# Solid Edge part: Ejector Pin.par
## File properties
Title: Ejector Pin
Author: Dan
Template: FH Insert .par
Last saved by: Dan
Revision: 29
Application: Solid Edge
Density: 7833.000 kg/m^3
Accuracy: 0.990
Material: Steel
Face Style: Steel
Fill Style: ANSI32(Steel)
Virtual Style: Machined steel
Coef. of Thermal Exp: 1.3e-05
Thermal Conductivity: 32.0
Specific Heat: 481.0
Modulus of Elasticity: 199947953000.0
Poisson's Ratio: 0.29
Yield Stress: 262000766.0
Ultimate Stress: 358527364.0
Elongation: 0.0
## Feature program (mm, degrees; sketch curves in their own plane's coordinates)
sketch for "unnamed Protrusion 1" plane through (0, 0, 0) normal (1, 0, 0) x-axis (0, 1, 0)
extrude "unnamed Protrusion 1" add finite 136.2 along -normal
sketch for "ExtrudedProtrusion_4" plane through (-136.2, 0, 0) normal (-1, 0, 0) x-axis (0, -1, 0)
extrude "ExtrudedProtrusion_4" add finite 5 along -normal
sketch for "ExtrudedProtrusion_5" plane through (-136.2, 0, 0) normal (-1, 0, 0) x-axis (0, -1, 0)
extrude "ExtrudedProtrusion_5" add finite 50 along -normal
chamfer "Chamfer_1" setback 5
sketch for "Hole_2" plane through (-136.2, 0, 0) normal (-1, 0, 0) x-axis (0, 0, -1)
  circle centre (0, 0) radius 12.5
hole "Hole_2" finite
sketch for "ExtrudedCutout_3" plane through (-136.2, 0, 0) normal (-1, 0, 0) x-axis (0, 0, -1)
  circle centre (0, 0) radius 12.5
extrude "ExtrudedCutout_3" cut finite 2.2 along -normal
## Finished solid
Body 1: solid body, 12 faces, 11 edges, 1 vertex.
  Faces by surface: cylinder 5, plane 5, cone 2
  Edges by curve: circle 11
Bounding box of the edges (mm): 136.200 x 45.000 x 45.000, from (-136.2, -22.5, -22.5) to (0, 22.5, 22.5).
Cylindrical faces by radius (mm): R9 x1, R12.5 x2, R19.5 x1, R22.5 x1
Conical faces (half-angle, radius in mm at the cone's reference point): 45 deg R14.5 x1, 59 deg R9 x1
Planar faces by outward normal: +x 3, -x 2
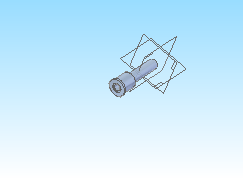
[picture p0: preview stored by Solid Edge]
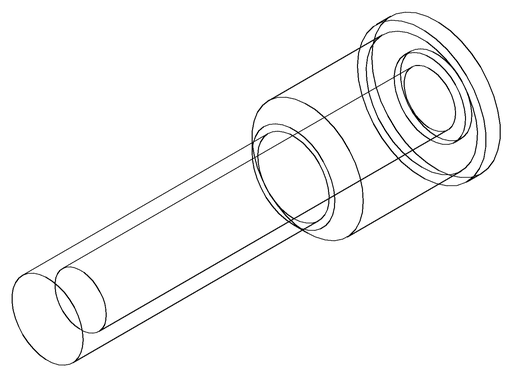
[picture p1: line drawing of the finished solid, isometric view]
